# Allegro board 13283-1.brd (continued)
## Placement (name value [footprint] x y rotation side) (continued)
R2421  100KR2J-1-GP  [R402H16]  172.67 32.2 90 bottom
R2422  0R0402-PAD-2-GP  [0R0402-PAD-1]  158.07 25.06 90 top
R2423  0R0402-PAD-2-GP  [0R0402-PAD-1]  158.08 25.96 90 top
R2424  0R2J-2-GP  [R402H16]  156.92 27.26 180 top
R2425  330KR2J-L1-GP  [R402H16]  162 27.5 90 bottom
R2426  100KR2J-1-GP  [R402H16]  159.71 38.42 270 top
R2427  0R0402-PAD-2-GP  [0R0402-PAD-1]  162.89 28.39 90 bottom
R2428  0R0402-PAD-2-GP  [0R0402-PAD-1]  167.84 25.98 90 bottom
R2429  100KR2J-1-GP  [R402H16]  164.03 30.8 0 bottom
R2430  0R0402-PAD-2-GP  [0R0402-PAD-1]  158.19 33.8 0 top
R2431  330KR2J-L1-GP  [R402H16]  154.63 29.66 90 top
R2432  1KR2J-1-GP  [R402H16]  153.24 29.28 0 top
R2433  20KR2F-L-GP  [R402H16]  152.35 29.28 180 top
R2434  0R2J-2-GP  [R402H16]  167.43 27.56 180 bottom
R2435  0R0402-PAD-2-GP  [0R0402-PAD-1]  166.71 19.28 0 top
R2436  10KR2J-3-GP  [R402H16]  167.41 29.3 0 bottom
R2437  100KR2J-1-GP  [R402H16]  166.44 43.38 0 top
R2438  0R0402-PAD-2-GP  [0R0402-PAD-1]  182.44 35.32 0 top
R2439  10KR2J-3-GP  [R402H16]  154.25 24.38 90 top
R2440  0R0402-PAD-2-GP  [0R0402-PAD-1]  187.2 35.69 180 top
R2441  10KR2J-3-GP  [R402H16]  173.94 27.88 0 bottom
R2442  100KR2J-1-GP  [R402H16]  181.55 35.33 180 top
R2443  10KR2J-3-GP  [R402H16]  184.48 26.48 270 top
R2444  0R0402-PAD-2-GP  [0R0402-PAD-1]  181.69 28.2 270 top
R2445  100KR2J-1-GP  [R402H16]  181.69 27.38 90 top
R2446  64K9R2F-1-GP  [R402H16]  159.85 19.73 270 top
R2447  1KR2J-1-GP  [R402H16]  159.71 37.53 90 top
R2448  0R0402-PAD-2-GP  [0R0402-PAD-1]  32.83 83.92 0 bottom
R2449  0R0402-PAD-2-GP  [0R0402-PAD-1]  45.35 79.33 0 top
R2501  10KR2J-3-GP  [R402H16]  146.76 38.8 180 bottom
R2502  1KR2J-1-GP  [R402H16]  52.3 7.89 180 bottom
R2504  10MR2J-L-GP  [R402H16]  51.76 10.23 90 bottom
R2601  0R2J-2-GP  [R402H16]  122.25 59.5 90 top
R2602  0R2J-2-GP  [R402H16]  156.23 23.99 180 top
R2603  18K7R2F-GP  [R402H16]  127.84 61.03 270 top
R2604  2KR2F-3-GP  [R402H16]  119.07 60.39 90 top
R2605  0R2J-2-GP  [R402H16]  37.41 95.83 90 bottom
R2606  0R0402-PAD-2-GP  [0R0402-PAD-1]  41.09 93.92 180 bottom
R2607  0R3J-0-U-GP  [R603H22]  170 21.66 90 bottom
R2610  NTC-100K-8-GP  [NTC-603H38]  127.96 63.82 180 top
R2611  24K3R2F-1-GP  [R402H16]  129.11 61.54 180 top
R2612  0R0402-PAD-2-GP  [0R0402-PAD-1]  169.87 26.1 270 bottom
R2622  24K3R2F-1-GP  [R402H16]  129.99 61.54 180 top
R2624  2KR2F-3-GP  [R402H16]  171.02 22.8 90 bottom
R2701  0R0402-PAD-2-GP  [0R0402-PAD-1]  29.64 5.91 0 bottom
R2702  0R0805-PAD-2-GP-U  [0R0805-PAD-1-U]  45.09 3.55 270 top
R2703  0R0603-PAD-2-GP-U  [0R0603-PAD-1-U]  25.09 22.17 0 bottom
R2704  0R0805-PAD-2-GP-U  [0R0805-PAD-1-U]  45.09 5.45 270 top
R2705  0R0402-PAD-2-GP  [0R0402-PAD-1]  31.49 4.39 180 top
R2706  0R0805-PAD-2-GP-U  [0R0805-PAD-1-U]  37.08 20.24 90 top
R2707  20KR2F-L-GP  [R402H16]  37.03 15.94 180 top
R2708  0R0402-PAD-2-GP  [0R0402-PAD-1]  41.91 4.69 270 top
R2709  200KR2F-L-GP  [R402H16]  37.92 15.94 180 top
R2711  100KR2J-1-GP  [R402H16]  29.79 13.4 180 bottom
R2712  0R0402-PAD-2-GP  [0R0402-PAD-1]  30.67 20.92 180 top
R2714  0R0402-PAD-2-GP  [0R0402-PAD-1]  41.37 7.69 270 top
R2716  100R2J-2-GP  [R402H14]  41.37 8.53 270 top
R2717  1KR2J-1-GP  [R402H16]  39.62 17.19 270 top
R2718  0R0402-PAD-2-GP  [0R0402-PAD-1]  41.86 12.77 270 top
R2719  0R0402-PAD-2-GP  [0R0402-PAD-1]  40.08 10.61 90 bottom
R2720  0R0402-PAD-2-GP  [0R0402-PAD-1]  41.32 10.49 270 top
R2722  100KR2J-1-GP  [R402H16]  37.36 14.04 270 bottom
R2901  0R0603-PAD-2-GP-U  [0R0603-PAD-1-U]  79.45 2.68 270 top
R2902  0R0603-PAD-2-GP-U  [0R0603-PAD-1-U]  79.51 4.35 270 top
R2903  0R0603-PAD-2-GP-U  [0R0603-PAD-1-U]  79.37 7.59 270 top
R2904  0R0603-PAD-2-GP-U  [0R0603-PAD-1-U]  79.37 6.24 270 top
R2905  100KR2J-1-GP  [R402H16]  19.63 8.58 180 bottom
R2906  0R0603-PAD-2-GP-U  [0R0603-PAD-1-U]  18.11 5.15 180 top
R2907  0R0603-PAD-2-GP-U  [0R0603-PAD-1-U]  25.73 4.77 180 top
R2908  10R2F-L-GP  [R402H14]  29.3 9.73 270 top
R2909  0R0603-PAD-2-GP-U  [0R0603-PAD-1-U]  26.49 7.43 90 top
R2910  10R2F-L-GP  [R402H14]  27.63 8.58 270 top
R2911  0R0603-PAD-2-GP-U  [0R0603-PAD-1-U]  25.47 11.88 90 top
R2912  4K7R2J-2-GP  [R402H16]  29.3 10.62 270 top
R2913  4K7R2J-2-GP  [R402H16]  27.76 12.22 270 top
R2914  0R0603-PAD-2-GP-U  [0R0603-PAD-1-U]  22.17 10.86 270 bottom
R2915  470KR2J-2-GP  [R402H16]  31.06 19.5 90 bottom
R2917  0R2J-2-GP  [R402H16]  41.35 16.32 270 top
R2918  100KR2J-1-GP  [R402H16]  37.51 18 90 top
R2919  10KR2J-3-GP  [R402H16]  26.87 15.56 90 top
R2920  10KR2J-3-GP  [R402H16]  26.36 18.1 180 top
R2921  1KR2J-1-GP  [R402H16]  27.25 18.1 0 top
R2922  1KR2J-1-GP  [R402H16]  26.87 16.83 270 top
R2924  0R0402-PAD-2-GP  [0R0402-PAD-1]  18.49 8.7 0 top
R2925  10KR2J-3-GP  [R402H16]  19.38 8.7 180 top
R3001  0R3J-0-U-GP  [R603H22]  27.83 40.16 180 bottom
R3003  10KR2J-3-GP  [R402H16]  38.3 41.6 180 top
R3004  10KR2J-3-GP  [R402H16]  43.25 41.98 180 top
R3005  0R0402-PAD-2-GP  [0R0402-PAD-1]  43.25 43.76 0 top
R3006  0R0603-PAD-2-GP-U  [0R0603-PAD-1-U]  32.77 38.31 0 bottom
R3014  1KR2J-1-GP  [R402H16]  37.41 41.6 180 top
R3015  15KR2J-1-GP  [R402H16]  36.52 42.23 180 top
R3016  0R0603-PAD-2-GP-U  [0R0603-PAD-1-U]  37.16 38.42 270 top
R3021  10KR2J-3-GP  [R402H16]  44.9 47.82 0 top
R3022  20KR2J-L2-GP  [R402H16]  43.63 47.44 270 top
R3023  100KR2J-1-GP  [R402H16]  46.81 52.27 0 top
R3032  2K49R2F-GP  [R402H16]  30.39 48.31 270 bottom
R3033  10KR2J-3-GP  [R402H16]  35.94 38.27 180 bottom
R3408  0R0402-PAD-2-GP  [0R0402-PAD-1]  24.61 28.49 270 bottom
R3409  0R0402-PAD-2-GP  [0R0402-PAD-1]  24.61 27.47 270 bottom
R3410  0R0402-PAD-2-GP  [0R0402-PAD-1]  28.09 25.65 270 bottom
R3411  0R0402-PAD-2-GP  [0R0402-PAD-1]  28.09 24.79 270 bottom
R3501  100KR2J-1-GP  [R402H16]  19.84 27.12 0 top
R3502  100KR2J-1-GP  [R402H16]  160.22 5 180 bottom
R3602  200KR2J-L1-GP  [R402H16]  152.06 24.25 180 top
R3603  1KR2J-1-GP  [R402H16]  151.24 24.25 180 top
R3604  0R0402-PAD-2-GP  [0R0402-PAD-1]  137.36 65.47 180 top
R3605  0R0402-PAD-2-GP  [0R0402-PAD-1]  138.25 65.47 180 top
R3609  0R0402-PAD-2-GP  [0R0402-PAD-1]  131.82 10.64 180 top
R3624  1KR2J-1-GP  [R402H16]  137.87 63.19 270 top
R3625  100KR2J-1-GP  [R402H16]  29.08 22.57 180 top
R3626  100KR2J-1-GP  [R402H16]  29.08 24.3 180 top
R3627  0R0402-PAD-2-GP  [0R0402-PAD-1]  138.5 61.03 270 top
R5201  0R0402-PAD-2-GP  [0R0402-PAD-1]  34.36 81.22 90 top
R5202  100KR2J-1-GP  [R402H16]  52.47 75.43 90 top
R5203  0R0402-PAD-2-GP  [0R0402-PAD-1]  32.18 79.86 0 top
R5204  0R0402-PAD-2-GP  [0R0402-PAD-1]  31.34 79.86 0 top
R5205  0R0402-PAD-2-GP  [0R0402-PAD-1]  34.81 83.88 0 bottom
R5206  0R0402-PAD-2-GP  [0R0402-PAD-1]  43.38 88.71 90 bottom
R5207  0R2J-2-GP  [R402H16]  19.73 86.94 270 bottom
R5208  10KR2J-3-GP  [R402H16]  36.4 86.56 0 bottom
R5209  0R2J-2-GP  [R402H16]  37.28 86.56 180 bottom
R5210  100R2J-2-GP  [R402H14]  35.51 86.56 0 bottom
R5211  0R5J-5-GP  [R805H24]  46.99 78.07 0 top
R5219  0R2J-2-GP  [R402H16]  29.02 88.2 270 bottom
R5221  0R2J-2-GP  [R402H16]  29.02 89.21 270 bottom
R5222  0R0402-PAD-2-GP  [0R0402-PAD-1]  41.6 88.71 270 bottom
R5229  0R3J-0-U-GP  [R603H22]  33.5 68.6 270 top
R5230  0R0603-PAD-2-GP-U  [0R0603-PAD-1-U]  31.95 70.55 180 top
R5231  0R3J-0-U-GP  [R603H22]  33.25 70.56 180 top
R5232  0R3J-0-U-GP  [R603H22]  29.76 77.25 90 top
R5233  100R2J-2-GP  [R402H14]  44.47 77.72 0 top
R5401  0R0402-PAD-2-GP  [0R0402-PAD-1]  16.71 78.55 90 bottom
R5402  0R0402-PAD-2-GP  [0R0402-PAD-1]  16.71 77.67 90 bottom
R5403  0R0402-PAD-2-GP  [0R0402-PAD-1]  16.71 80.71 90 bottom
R5404  0R0402-PAD-2-GP  [0R0402-PAD-1]  16.71 79.82 90 bottom
R5405  0R0402-PAD-2-GP  [0R0402-PAD-1]  16.71 84.9 90 bottom
R5406  0R0402-PAD-2-GP  [0R0402-PAD-1]  16.71 84.02 90 bottom
R5407  0R0402-PAD-2-GP  [0R0402-PAD-1]  16.71 82.87 90 bottom
R5408  0R0402-PAD-2-GP  [0R0402-PAD-1]  16.71 81.98 90 bottom
R5409  0R3J-0-U-GP  [R603H22]  24.33 91.89 90 bottom
R5410  200KR2F-L-GP  [R402H16]  48.97 56.33 90 bottom
R5411  150KR2F-L-GP  [R402H16]  48.97 55.44 90 bottom
R5412  10KR2J-3-GP  [R402H16]  48.97 54.55 270 bottom
R5413  100KR2J-1-GP  [R402H16]  24.2 76.9 270 top
R5414  150R2J-L1-GP-U  [R402H16]  15.31 78.05 180 bottom
R5415  150R2J-L1-GP-U  [R402H16]  15.31 84.4 180 bottom
R5416  150R2J-L1-GP-U  [R402H16]  15.31 80.33 180 bottom
R5417  150R2J-L1-GP-U  [R402H16]  15.31 82.49 180 bottom
R5418  0R2J-2-GP  [R402H16]  21.92 81.48 270 top
R5419  0R0402-PAD-2-GP  [0R0402-PAD-1]  48.97 53.66 90 bottom
R5602  0R0402-PAD-2-GP  [0R0402-PAD-1]  195.53 82.11 90 bottom
R5604  10KR2J-3-GP  [R402H16]  198.19 78.05 0 top
R5610  100KR2J-1-GP  [R402H16]  197.32 78.02 0 top
R5801  0R2J-2-GP  [R402H16]  191.34 24.58 0 top
R5802  0R0402-PAD-2-GP  [0R0402-PAD-1]  172.03 16.76 90 bottom
R5803  0R0402-PAD-2-GP  [0R0402-PAD-1]  172.03 15.89 270 bottom
R5804  0R2J-2-GP  [R402H16]  168.98 20.26 270 top
R5805  0R0402-PAD-2-GP  [0R0402-PAD-1]  190.45 24.58 0 top
R5806  0R2J-2-GP  [R402H16]  189.56 26.36 0 top
R5807  0R2J-2-GP  [R402H16]  192.22 24.58 0 top
R5808  10KR2J-3-GP  [R402H16]  185.62 39.95 90 top
R6101  330R2J-3-GP  [R402H16]  180.06 17.87 270 top
R6102  100R2J-2-GP  [R402H14]  96.34 141.44 180 bottom
R6103  499R2F-2-GP  [R402H16]  180.06 17.04 270 top
R6104  0R0402-PAD-2-GP  [0R0402-PAD-1]  176.91 19.42 180 top
R6105  0R0402-PAD-2-GP  [0R0402-PAD-1]  171.14 19.83 90 top
R6201  1KR2J-1-GP  [R402H16]  193.75 87.57 180 top
R6202  0R0402-PAD-2-GP  [0R0402-PAD-1]  193.75 85.79 180 top
R6205  0R3J-0-U-GP  [R603H22]  124.41 101.41 0 top
R6206  51KR2J-1-GP  [R402H16]  140.92 78.05 180 top
R6207  100KR2J-1-GP  [R402H16]  141.81 78.05 180 top
R6208  100KR2J-1-GP  [R402H16]  133.42 64.84 90 top
R6209  0R0603-PAD-2-GP-U  [0R0603-PAD-1-U]  136.98 79.32 270 top
R6210  0R0402-PAD-2-GP  [0R0402-PAD-1]  132.88 79.08 180 top
R6211  0R0402-PAD-2-GP  [0R0402-PAD-1]  133.8 79.06 180 top
R6212  0R0402-PAD-2-GP  [0R0402-PAD-1]  129.16 96.46 270 bottom
R6213  0R0402-PAD-2-GP  [0R0402-PAD-1]  129.16 97.32 270 bottom
R6303  0R0402-PAD-2-GP  [0R0402-PAD-1]  171.65 14.04 270 top
R6304  0R0402-PAD-2-GP  [0R0402-PAD-1]  171.65 15.05 90 top
R6501  0R2J-2-GP  [R402H16]  160.23 13.55 0 top
R6502  0R2J-2-GP  [R402H16]  158.82 15.31 270 top
R7301  3KR2J-2-GP  [R402H16]  174.83 118.69 180 top
R7304  10KR2J-3-GP  [R402H16]  172.39 118.94 90 top
R7305  10KR2J-3-GP  [R402H16]  180.79 117.8 270 bottom
R7311  5K1R2F-2-GP  [R402H16]  180.79 123.13 270 bottom
R7314  100KR2J-L-GP  [R402H16]  172.39 117.97 90 top
R7315  10KR2J-3-GP  [R402H16]  180.79 116.15 0 bottom
R7317  1KR2F-3-GP  [R402H16]  171.52 121.99 0 top
R7318  1KR2F-3-GP  [R402H16]  158.06 116.15 180 top
R7320  0R0402-PAD-2-GP  [0R0402-PAD-1]  158.82 99.84 270 bottom
R7321  1K69R2F-2-GP  [R402H16]  158.9 116.15 180 top
R7322  10KR2J-3-GP  [R402H16]  182.7 118.81 180 bottom
R7323  10KR2J-3-GP  [R402H16]  182.06 121.35 270 bottom
R7324  10KR2J-3-GP  [R402H16]  180.79 122.24 270 bottom
R7325  10KR2J-3-GP  [R402H16]  183.97 120.72 270 bottom
R7326  0R0402-PAD-2-GP  [0R0402-PAD-1]  164.21 98.52 180 bottom
R7327  10KR2J-3-GP  [R402H16]  164.21 100.25 180 bottom
R7332  1KR2F-3-GP  [R402H16]  180.79 124.02 90 bottom
R7401  2K2R2J-2-GP  [R402H16]  173.05 152.72 270 top
R7402  49D9R2F-GP  [R402H16]  171.78 153.1 0 top
R7404  5K1R2F-2-GP  [R402H16]  173.05 154.5 270 top
R7408  120R2F-GP  [R402H16]  155.01 121.86 90 top
R7409  120R2F-GP  [R402H16]  159.08 122.75 270 top
R7410  40D2R2F-GP  [R402H16]  149.04 125.67 90 top
R7411  40D2R2F-GP  [R402H16]  149.04 126.69 90 top
R7414  100R2F-L1-GP-U  [R402H14]  151.2 125.29 0 top
R7415  100R2F-L1-GP-U  [R402H14]  150.31 127.07 180 top
R7418  51R2F-2-GP  [R402H16]  181.3 118.69 270 bottom
R7419  51R2F-2-GP  [R402H16]  175.87 123.26 90 top
R7420  10R2J-2-GP  [R402H14]  171.78 154.88 0 top
R7424  10KR2J-L-GP  [R402H15]  179.91 116.15 0 bottom
R7425  10KR2J-3-GP  [R402H16]  179.02 116.15 180 bottom
R7501  100KR2J-1-GP  [R402H16]  182.06 120.08 90 bottom
R7510  10KR2J-3-GP  [R402H16]  181.68 116.15 0 bottom
R7517  8K45R2F-2-GP  [R402H16]  161.36 109.29 270 top
R7518  0R0402-PAD-2-GP  [0R0402-PAD-1]  185.87 115.51 90 bottom
R7519  0R2J-2-GP  [R402H16]  180.16 113.48 270 bottom
R7520  4K75R2F-1-GP  [R402H16]  161.36 102.89 180 bottom
R7521  8K45R2F-2-GP  [R402H16]  161.36 110.18 270 top
R7522  2KR2F-3-GP  [R402H16]  161.36 111.07 270 top
R7523  8K45R2F-2-GP  [R402H16]  164.21 105.22 0 top
R7524  4K75R2F-1-GP  [R402H16]  160.47 108.02 0 top
R7526  4K75R2F-1-GP  [R402H16]  165.63 108.58 90 top
R7527  8K45R2F-2-GP  [R402H16]  163.45 103.29 270 bottom
R7533  10KR2J-3-GP  [R402H16]  184.1 115.51 270 bottom
R7710  150R2F-4-L-GP  [R402H16]  166.09 109.49 90 top
R7727  1MR2J-1-GP  [R402H16]  154.89 103.24 90 bottom
R7801  243R2F-2-GP  [R402H16]  159.33 137.23 0 bottom
R7802  243R2F-2-GP  [R402H16]  156.79 153.23 0 top
R7803  40D2R2F-GP  [R402H16]  156.79 153.23 0 bottom
R7804  40D2R2F-GP  [R402H16]  157.68 153.23 0 bottom
R7805  2K1R2F-GP  [R402H16]  153.74 152.85 270 bottom
R7806  2K1R2F-GP  [R402H16]  155.01 153.23 0 bottom
R8301  0R2J-2-GP  [R402H16]  135.89 102.05 0 bottom
R8309  15KR2J-1-GP  [R402H16]  134.62 101.59 270 bottom
R8310  15KR2J-1-GP  [R402H16]  134.62 102.48 270 bottom
R8901  2K1R2F-GP  [R402H16]  176.35 152.85 90 top
R8902  2K1R2F-GP  [R402H16]  177.62 153.23 180 top
R8903  243R2F-2-GP  [R402H16]  176.73 153.23 180 bottom
R8904  243R2F-2-GP  [R402H16]  176.98 137.23 180 top
R8907  40D2R2F-GP  [R402H16]  179.4 153.23 0 bottom
R8908  40D2R2F-GP  [R402H16]  180.29 153.23 0 bottom
RJ45  RJ45-8P-165-GP  [C100HR-10805-L]  7.88 62.7 90 bottom
RN401  SRN2K2J-1-GP  [ARES2H16]  70.94 79.82 270 bottom
RN402  SRN4K7J-8-GP  [SMD-ARES4H18]  67.13 87.57 90 top
RN404  SRN1KJ-4-GP  [ARES8-CN24H20]  65.1 77.79 90 top
RN405  SRN1KJ-4-GP  [ARES8-CN24H20]  68.53 81.73 270 top
RN407  SRN1KJ-4-GP  [ARES8-CN24H20]  65.1 80.59 270 top
RN408  SRN1KJ-11-GP-U  [SMD-ARES4-2H18-U]  77.04 83.38 270 bottom
RN601  SRN2K2J-1-GP  [ARES2H16]  120.22 78.43 270 bottom
RN602  SRN100KJ-6-GP  [SMD-ARES4]  123.77 87.7 90 bottom
RN603  SRN10KJ-5-GP  [ARES2H18]  117.29 86.56 0 bottom
RN604  SRN10KJ-6-GP  [ARES8-CN24-MUH20]  116.46 97.43 270 bottom
RN1901  0R8P4R-PAD-1-GP  [0R8P4R-PAD-1]  112.09 99.38 270 bottom
RN1902  -  [0R4P2R-PAD]  99.64 98.49 0 bottom
RN1903  -  [0R4P2R-PAD]  70.18 76.9 90 bottom
RN1904  SRN10KJ-5-GP  [ARES2H18]  119.45 90.11 180 top
RN1905  -  [0R4P2R-PAD]  96.72 98.75 0 bottom
RN2401  SRN4K7J-8-GP  [SMD-ARES4H18]  156.34 38.98 180 top
RN2501  SRN10KJ-5-GP  [ARES2H18]  152.06 36.59 0 bottom
RN2601  SRN0J-6-GP  [SMD-ARES4H20]  63.07 81.86 180 top
RN2602  SRN2K2J-1-GP  [ARES2H16]  65.86 84.78 270 top
RN2701  -  [0R4P2R-PAD]  40.59 23.18 180 top
RN2901  SRN2K2J-1-GP  [ARES2H16]  34.59 18.05 180 top
RN3001  SRN10KJ-5-GP  [ARES2H18]  37.46 35.98 270 top
RN3101  SRN75J-1-GP  [ARES8-CN24H22]  21.92 46.93 180 top
RN4301  SRN100J-4-GP  [ARES8-CN24H20]  137.61 142.94 0 top
RN5201  SRN100J-4-GP  [ARES8-CN24H20]  39.57 87.19 90 bottom
RN5202  SRN33J-5-GP-U  [SMD-ARES4H18]  28.09 85.8 90 bottom
RN5203  SRN100KJ-5-GP  [ARES8-CN24H20]  46.17 74.62 0 top
RN5204  SRN33J-5-GP-U  [SMD-ARES4H18]  32.41 85.78 270 bottom
RN5205  SRN0J-6-GP  [SMD-ARES4H20]  42.11 66.11 90 bottom
RN5206  -  [0R4P2R-PAD]  42.11 66.11 270 top
RN5401  SRN2K2J-1-GP  [ARES2H16]  21.99 90.8 0 bottom
RN5402  SRN499F-GP  [ARES8-CN24H20]  20.01 83.13 90 top
RN5403  SRN499F-GP  [ARES8-CN24H20]  20.01 79.57 90 top
RN5404  SRN2K2J-1-GP  [ARES2H16]  15.47 91.25 270 bottom
RN5601  SRN10KJ-5-GP  [ARES2H18]  194.89 79.95 180 bottom
RN6201  SRN4K7J-8-GP  [SMD-ARES4H18]  122.12 97.6 270 bottom
RN6203  SRN10KJ-5-GP  [ARES2H18]  136.6 76.93 90 top
RN6501  SRN0J-7-GP-U  [ARES8-CN24H22]  162.1 13.7 180 top
RN6502  SRN10KJ-6-GP  [ARES8-CN24-MUH20]  53.39 68.09 90 top
RN7501  SRN4K7J-8-GP  [SMD-ARES4H18]  181.18 107.76 180 bottom
RTC1  BAT-060003HA002M213ZL-GP-U1  [060003HA002M213ZL-U2]  60.75 12.32 180 top
S1  STF237R117H83-1-GP  [STF237R117H83]  200.02 96.03 180 bottom
S2  STF237R117H83-1-GP  [STF237R117H83]  141.32 131.36 180 bottom
SPI25  W25Q64FVSSIQ-GP  [SOIC8-1H86]  149.3 44.77 90 bottom
SPK1  ACES-CON4-29-GP  [50224-0040N-001]  86.55 2.4 0 top
SPR2  SPRING-102-GP  [SPR5930H154]  49.9 40.71 0 top
SPR4  SPRING-43-GP-U  [SPR4527H308]  123.2 51.9 180 bottom
SPR5  SPRING-102-GP  [SPR5930H154]  56.9 77.7 0 bottom
SPR6  SPRING-57-GP  [SPR9537H308]  72.92 13.93 0 bottom
SW1  ETY-CON4-34-GP  [6916K-Q04M-00L]  94.9 135.7 270 top
TC3501  SC100U6D3V6MX-GP  [C1206H71]  19.17 30.29 180 top
TC3502  SC100U6D3V6MX-GP  [C1206H71]  19.94 39.95 0 top
TC6301  SC100U6D3V6MX-GP  [C1206H71]  182.22 5.86 180 bottom
THM26  W83L771AWG-2-GP  [MSOP8-1H44]  123.26 62.04 270 top
TP401  TPAD14-OP-GP  [TPAD14-OP]  90.7 79.24 0 top
TP402  TPAD14-OP-GP  [TPAD14-OP]  90.45 77.92 0 top
TP403  TPAD14-OP-GP  [TPAD14-OP]  87.07 80.46 0 top
TP404  TPAD14-OP-GP  [TPAD14-OP]  78.43 77.28 180 bottom
TP409  TPAD14-OP-GP  [TPAD14-OP]  89.23 75.91 0 top
TP410  TPAD14-OP-GP  [TPAD14-OP]  107.9 75 0 top
TP411  TPAD14-OP-GP  [TPAD14-OP]  106.63 75 0 top
TP416  TPAD14-OP-GP  [TPAD14-OP]  103.2 88.97 0 top
TP417  TPAD14-OP-GP  [TPAD14-OP]  101.95 90.82 0 top
TP418  TPAD14-OP-GP  [TPAD14-OP]  94.31 77.32 0 top
TP420  TPAD14-OP-GP  [TPAD14-OP]  93.16 76.4 0 top
TP421  TPAD14-OP-GP  [TPAD14-OP]  105.23 78.17 0 top
TP433  TPAD14-OP-GP  [TPAD14-OP]  88.34 82.62 0 top
TP434  TPAD14-OP-GP  [TPAD14-OP]  87.2 81.73 0 top
TP1901  TPAD14-OP-GP  [TPAD14-OP]  110.44 97.48 180 bottom
TP1902  TPAD14-OP-GP  [TPAD14-OP]  110.44 77.79 0 top
TP1903  TPAD14-OP-GP  [TPAD14-OP]  107.36 97.48 180 bottom
TP1904  TPAD14-OP-GP  [TPAD14-OP]  105.23 91.76 0 top
TP2401  TPAD14-OP-GP  [TPAD14-OP]  166.9 30.8 180 bottom
TP2402  TPAD14-OP-GP  [TPAD14-OP]  166.04 28.19 180 bottom
TP2702  TPAD14-OP-GP  [TPAD14-OP]  39.03 6.08 270 top
TP3001  TPAD14-OP-GP  [TPAD14-OP]  27.84 42.01 270 bottom
TP3002  TPAD14-OP-GP  [TPAD14-OP]  26.69 42.58 90 bottom
TP3003  TPAD14-OP-GP  [TPAD14-OP]  32.42 43.31 90 bottom
TP5801  TPAD14-OP-GP  [TPAD14-OP]  191.45 44.29 180 bottom
TP5802  TPAD14-OP-GP  [TPAD14-OP]  191.14 32.9 180 bottom
TP5803  TPAD14-OP-GP  [TPAD14-OP]  178.43 21.81 180 bottom
TP5804  TPAD14-OP-GP  [TPAD14-OP]  178.46 20.57 180 bottom
TP7501  TPAD14-OP-GP  [TPAD14-OP]  165.86 111.65 0 top
TP7502  TPAD14-OP-GP  [TPAD14-OP]  180.54 119.83 180 bottom
TP7503  TPAD14-OP-GP  [TPAD14-OP]  179.27 119.83 180 bottom
TP7504  TPAD14-OP-GP  [TPAD14-OP]  179.27 123.64 180 bottom
TP7505  TPAD14-OP-GP  [TPAD14-OP]  180.54 121.1 180 bottom
TP7506  TPAD14-OP-GP  [TPAD14-OP]  179.27 121.1 180 bottom
TP7507  TPAD14-OP-GP  [TPAD14-OP]  172.54 120.21 0 top
TP7508  TPAD14-OP-GP  [TPAD14-OP]  179.27 122.37 180 bottom
TP7509  TPAD14-OP-GP  [TPAD14-OP]  179.27 117.67 180 bottom
TP7510  TPAD14-OP-GP  [TPAD14-OP]  165.55 112.84 0 top
TP7511  TPAD14-OP-GP  [TPAD14-OP]  171.27 116.65 0 top
TP7514  TPAD14-OP-GP  [TPAD14-OP]  171.4 106.75 0 top
TP7515  TPAD14-OP-GP  [TPAD14-OP]  171.52 105.48 0 top
TP7516  TPAD14-OP-GP  [TPAD14-OP]  159.59 111.45 0 top
TP7517  TPAD14-OP-GP  [TPAD14-OP]  180.67 114.5 180 bottom
TP7518  TPAD14-OP-GP  [TPAD14-OP]  179.4 114.5 180 bottom
TP7522  TPAD14-OP-GP  [TPAD14-OP]  163.14 110.46 0 top
TP7703  TPAD14-OP-GP  [TPAD14-OP]  150.82 127.58 180 bottom
TP7704  TPAD14-OP-GP  [TPAD14-OP]  175.46 103.07 180 bottom
TP7705  TPAD14-OP-GP  [TPAD14-OP]  150.95 106.37 180 bottom
TPAD1  ACES-CON8-40-GP  [50505-0084N-002]  132.4 91.3 0 top
TR3401  FILTER-4P-6-GP  [FILTER2013-4P-1H44]  22.93 40.88 180 bottom
TR3404  FILTER-4P-6-GP  [FILTER2013-4P-1H44]  25.4 25.89 180 top
TR5208  FILTER-4P-6-GP  [FILTER2013-4P-1H44]  29.02 88.7 180 bottom
TR5209  FILTER-4P-6-GP  [FILTER2013-4P-1H44]  36.01 76.03 90 top
TR6301  FILTER-4P-6-GP  [FILTER2013-4P-1H44]  176.22 13.15 0 top
U402  NC7WV07P6X-GP  [SC70-6H44]  73.99 83.51 90 bottom
U701  TLV70215DBVR-GP  [SOT-23-5H58]  119.45 100.65 180 top
U2901  2N7002KDW-GP  [SOT-363H44]  31.57 17.47 270 bottom
U3101  TVWDF1004AD0-1-GP  [DFN10G2510H26]  33.47 55.31 270 bottom
U3102  TVWDF1004AD0-1-GP  [DFN10G2510H26]  33.47 55.31 270 top
U3401  AZC099-04S-1-GP  [SOT-6H58]  18.67 40.87 270 bottom
U3402  TVWDF1004AD0-1-GP  [DFN10G2510H26]  19.56 25.6 270 bottom
U3403  AZC099-04S-1-GP  [SOT-6H58]  21.11 24.05 270 top
U3503  G524B2T11U-GP  [SOT-23-5H58]  32.2 32.68 270 top
U3504  G524B2T11U-GP  [SOT-23-5H58]  32.2 29.02 270 top
U3505  G524B2T11U-GP  [SOT-23-5H58]  149.42 4.36 180 bottom
U3601  TPS22966DPUR-GP  [SON14J3020-G2610H34]  131.69 6.83 0 top
U3602  TLV70215DBVR-GP  [SOT-23-5H58]  26.26 22.06 90 top
U3603  TPS22966DPUR-GP  [SON14J3020-G2610H34]  132.15 64.08 90 bottom
U5201  RT9724GB-GP  [SOT-23-5H51]  49.71 75.76 180 top
U5601  TPS2001CDGNR-GP  [MSOP8-1G189157H43]  194.51 75.63 0 top
U8201  74LVC1G08GW-1-GP  [SC70-5H44]  154.25 80.46 270 top
U8302  TPS22966DPUR-GP  [SON14J3020-G2610H34]  140.15 102.05 270 bottom
USB1  SKT-USB13-151-GP  [SKT-USB13-157164]  5.28 25.1 90 bottom
USB2  SKT-USB8-14-GP  [SKT-USB8-166140-2]  1.82 43.1 90 bottom
VRAM1  MT41K256M16HA-107G-E-GP  [BGA96D0914H48]  156.59 145.19 90 top
VRAM2  MT41K256M16HA-107G-E-GP  [BGA96D0914H48]  156.59 145.19 270 bottom
VRAM3  MT41K256M16HA-107G-E-GP  [BGA96D0914H48]  179.19 145.19 270 top
VRAM4  MT41K256M16HA-107G-E-GP  [BGA96D0914H48]  179.19 145.19 90 bottom
WLAN1  SKT-MINI52P-154-GP  [MM60-52B1-KT-R550-DT]  184.9 30.7 270 bottom
X601  XTAL-32D768KHZ-17-GP  [SMD49-6914-0403H56]  105.23 102.94 0 bottom
X1902  XTAL-48MHZ-27-GP-U  [OSC-3225-4P-4H36]  92.28 100.91 0 bottom
X3001  XTAL-25MHZ-155-GP  [OSC-3225-4P-3H36]  29.03 45.41 90 bottom
X7503  XTAL-27MHZ-46-GP  [SMD-OSC12H36]  154.76 101.03 180 bottom
XF3101  XFORM-12P-48-GP  [XFORM12A127097H91]  25.47 55.82 90 bottom
XF3102  XFORM-12P-48-GP  [XFORM12A127097H91]  25.47 55.82 270 top

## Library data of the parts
AFTP2501 AFTP2502 AFTP2801-AFTP2803 AFTP2901-AFTP2904 AFTP2906-AFTP2909 AFTP3101-AFTP3108 AFTP3801-AFTP3803 AFTP3805 AFTP3806 AFTP3901-AFTP3910 AFTP5201-AFTP5214 AFTP5222 AFTP5225-AFTP5228 AFTP6201-AFTP6242 AFTP6245-AFTP6248 AFTP6801 AFTP6802 = AFTE14P-75: tolerance: ZZ.AFT14.101
BAT1 = C144LC-109A7-L-U: tolerance: 20.81925.009
C1-C3 = HOLE197R166: tolerance: ZZ.00PAD.V71
C303-C306 C441 C445 C447 C448 C452 C457 C477 C478 = C402H22: tolerance: 78.10421.2FL; signal model: C402H22_SCD1U16V2KX-3GP
C401 C402 C601 = C402H22: tolerance: 78.15124.2FL
C443 C3405 C3406 C3504 = C402H22: tolerance: 78.10421.2FL
C501 C1201 C1204 C1214 C1217 C1222-C1225 C2402-C2404 C2406-C2410 C2412 C2414 C2417 C2502 C2602 C2605 C2608-C2610 C2615 C2707 C2709 C2710 C2717 C2719 C2720 C3002 C3009 C3013 C3507 C3517 C3625 C3626 C5201 C5401 C5606 C5802 C5804 C5807 C6202-C6204 C6402 C7406 C7407 C7515 C7631 C7681 C7686 C7689 C7779 C7781 C7788 C7791 C7803 C7808 C7810-C7814 C7816-C7819 C8308 C8309 C8313 C8314 C8901 C8908 C8910-C8915 C8920 C8922 C8923 EC2601 EC2703 EC2705 EC2708 EC2709 EC9739 EC9743 EC9744 PC4510 PC4525 PC4610 PC4612 PC4613 PC4617 PC4621 PC4906 PC8324 = C402H22: tolerance: 78.10423.2FL
C502 C1203 C1205 C1221 C3601 C3602 C3618 C3619 C5202 C8302 EC2704 EC2706 EC2707 EC9707 EC9709-EC9711 EC9714 EC9745 PC4601 PC4831 PC8213 = C402H22: tolerance: 78.10224.2FL
C603 = C402H22: tolerance: 78.8R064.1FL
C604 C5208 C5214 C7729 C7730 EC2503 EC2602 EC2701 EC3101-EC3108 EC4301 EC4302 EC4305 = C402H22: tolerance: 78.10034.1FL
C605 = C402H22: tolerance: 78.10422.L1L
C701 C702 C705 C3505 C3506 C3508 C3510 C3518 PC4901 PC4904 = C603H36: tolerance: 78.10523.5BL
C703 C762 C1208 C2501 C2601 C2712 C2713 C2902 C3603 C3605 C3620 C3621 C5609 C5610 C5803 C7582 C7602 C7610 C7613 C7623 C7634 C7640 C7652 C7679 C7682 C7684 C7687 C7792 C7793 C7801 C8303 C8304 C8905 PC4916 PC4917 PC5010-PC5012 PC5015 PC8321 PC8323 = C603H38: tolerance: 78.10610.5BL
C704 C1004-C1009 C1012-C1014 C1026-C1032 C1035-C1037 C1040-C1045 C1068-C1076 C1081-C1091 C1093-C1096 C1209-C1212 C2416 C2418 C2901 C5206 C7521 C7604 C7605 C7612 C7615-C7622 C7633 C7635-C7639 C7644-C7646 C7651 C7653 C7654 C7658-C7665 C7667-C7678 C7680 C7683 C7685 C7688 C7780 EC9718-EC9738 PC5013 = C402H22: tolerance: 78.10520.5FL
C1001 C1002 C1023 C1024 C2703 C2704 C3015 C3018 C3607 C3612 C3613 C3617 C7402 C7403 C8316 C8320 PC4528 PC4829 PC5005 = C402H22: tolerance: 78.10523.5FL
C1003 C1011 C1022 C1025 C1034 C1039 C1049-C1051 C1067 C1080 C1092 = C402H22: tolerance: 78.18134.1FL
C1010 C1015 C1016 C1033 C1038 C1046 C1053-C1055 C1215 C1216 C1218-C1220 C2604 C2611 C2701 C2702 C2706 C2708 C2711 C2715 C2716 C2718 C2907 C2908 C3004 C3005 C3010 C3012 C5204 C5207 PC4515 PC4516 PC4920 = C603H36: tolerance: 78.47520.5BL
C1047 C1064-C1066 C1077-C1079 C7647-C7650 C7666 = C603H40: tolerance: 78.22610.5BL
C1056-C1063 C3003 C3007 C3008 C3017 C3019 C3021-C3025 C3503 PC4620 PC4622 PC4701-PC4704 PC4834 PC4903 PC4915 PC4921 PC8211 PC8214 PC8217-PC8219 PC8234 PC8236 = C402H20: tolerance: 78.10423.5FL
C1202 C2705 C7607-C7609 C7624 C7625 = C402H22: tolerance: 78.22510.5FL
C1213 = C603H36: tolerance: 78.47520.L0L
C1904 C1905 EC5205 EC5206 = C402H22: tolerance: 78.6R864.1FL
C2405 C2411 C2413 PC4603 PC4604 PC8202 PC8203 = C603H36: tolerance: 78.22523.5BL
C2415 EC6103 EC6105 = C402H22: tolerance: 78.22124.2FL
C2421 C7333 PC4606 = C402H22: tolerance: 78.47034.1FL
C2503 PC4210 = C402H22: tolerance: 78.47420.5FL
C2603 C2607 EC4401 = C402H22: tolerance: 78.22224.2FL
C2606 = C603H36: tolerance: 78.47134.1BL
C2616 EC2905-EC2908 PC4605 PC4611 = C402H22: tolerance: 78.10134.1FL
C2723 PC4526 PC4527 PC5014 PC8208 = C402H22: tolerance: 78.22034.1FL
C3001 C3011 = C402H22: tolerance: 78.15034.1FL
C3014 C3016 C3403 C3404 C5203 C5209-C5213 C5402-C5409 C7301-C7308 = C402H22: tolerance: 78.10423.2FL; signal model: C402H22_SCD1U10V2KX-5GP
C3101 = C1808H56: tolerance: 78.1013N.1AL
C3106 PC4203-PC4205 PC4209 PC4412 PC4425 PC8224 PC8322 = C402H22: tolerance: 78.10324.2FL
C3401 C3402 EC2501 EC2502 = C402H22: tolerance: 78.4R774.1FL
C3509 C3512-C3516 PC4923-PC4926 = C805H58: tolerance: 78.22610.51L
C5205 EC4304 EC4601 PC4401 = C603H36: tolerance: 78.10422.2BL
C5602 C5603 C5607 C5608 C5611 C5612 C5615 C5616 = C402H22: tolerance: 78.10321.2FL; signal model: C402H22_SCD01U16V2KX-3GP
C5605 = C805H54: tolerance: 78.10623.51L
C6401 = C402H22: tolerance: 78.47321.2FL
C7401 = C402H22: tolerance: 78.12134.1FL
C7516 = C402H22: tolerance: 78.10322.L0L
C7517 = C402H22: tolerance: 78.82321.2FL
C7518 C7519 = C603H36: tolerance: 78.68421.5BL
C7611 C7802 C8903 PC4902 = C402H22: tolerance: 78.10321.2FL
C7787 C7790 = C402H22: tolerance: 78.10520.LAL
C8301 = C402H22: tolerance: 78.47124.2FL
CCD1 = 4260-F08N-00R: tolerance: 20.F1261.008
CPU1 = BGA769M24D5H78: tolerance: 071.BEEMA.000U
D401 D3602 D3603 = SOT23-2D4-312H44: tolerance: 83.00016.K11
D2401 D3606 = SOD323AKH38: tolerance: 83.R2004.G8F
D2501 = SOT23-2D4-312H48: tolerance: 75.00040.A7D
D2601 D5202 PD8201 PD8308 = SOD323AKH38: tolerance: 83.R5003.H8H
D2701 D5201 = SOT23-2D6-312H46: tolerance: 75.00054.K7D
D4301-D4303 PD4203 = SOT23-2D8-312H56: tolerance: 75.03101.07D
D5401 D7301 = SOT-23-9H44: tolerance: 83.00056.Q11
DB1 = PAD-10P-177042: tolerance: ZZ.00PAD.Y41
DCIN1 = 50299-00701-W01: tolerance: 20.F1783.007
DM1 = 1932208-1-U: tolerance: 62.10017.P41
EC2901-EC2904 = C603: tolerance: 78.22224.2BL
EC4303 EC4402 EC6104 EC9701 EC9703-EC9705 EC9708 EC9712 EC9713 EC9715-EC9717 EC9740-EC9742 EC9747-EC9749 PC4402 PC4420 PC4421 PC4423 = C402H22: tolerance: 78.10422.5FL
EC5210 EC6205-EC6208 = C402H22: tolerance: 78.33034.1FL
ED2901-ED2905 = SOD-523-4H28: tolerance: 75.02025.077
F5201 = POLYSW-4633-UH63: tolerance: 69.60040.001
F5203 = POLYSW-4633-UH43: tolerance: 69.50007.A31
F5401 = POLYSW-2114H30: tolerance: 69.48001.081
F6201 = POLYSW-2114H50: tolerance: 69.50007.921
FAN1 = 3703K-Q03N-11L: tolerance: 20.F1841.003
FAN261 = SOIC8H69: tolerance: 74.05606.A71
G701 = CON2O-U: tolerance: ZZ.CON2O.XXX
GPU1 = BGA631M23H82: tolerance: 71.SUNM2.M02
H1-H3 = HOLE335R115: tolerance: ZZ.00PAD.D01
H4 = HOLE256R115: tolerance: ZZ.00PAD.D11
H5 H6 = HT85BE85R29-U-5: tolerance: ZZ.00PAD.D41
HDA27 = QFN48J6-G465H40: tolerance: 71.03234.003
HDD1 = 127043HR022M25FZR: tolerance: 022.10019.0001
HDMI1 = SKT-HDMI23-188137: tolerance: 22.10296.A31
HDT1 = PAD-20P-127058: tolerance: ZZ.00PAD.0A1
HPMIC1 = 2SJ3080-036111F: tolerance: 022.10002.0001
IOBD1 = 196353-16021-3: tolerance: 20.K0382.016
KB1 KB2 = FL4S030HT6R300-DT: tolerance: 20.K0592.030
KBC24 = LQFP128H63: tolerance: 071.00285.000G
KBLIT1 = 51575-00441-W01: tolerance: 20.K0800.004
L3001 = L2520-D820H41: tolerance: 68.4R71E.10G
L7504 L7601 L7603 L7703 L7705 = L402H22: tolerance: 68.00084.B21
L7704 = L402H24: tolerance: 68.00094.991
L7706 L7707 PR4217 PR4911 R2402 R2703 R2901-R2904 R2906 R2907 R2909 R2911 R2914 R3006 R3016 R5230 R6209 = 0R0603-PAD-1-U: tolerance: ZZ.00PAD.M21
LCD1 = 51540-04001-W01: tolerance: 20.K0678.040
LIDSW1 = SOT23-2D8-123H52: tolerance: 74.05712.0BB
LOM30 = QFN32J4-G2D9-U1H36: tolerance: 71.08111.U03
ODD1 = C185A1-11305-L-U: tolerance: 20.81152.013
PC4010 = C603H36: tolerance: 78.47422.5BL
PC4201 = C805H58: tolerance: 78.10594.41L
PC4202 PC4409 PC4419 PC4511 PC4513 PC4518 PC4519 PC4524 PC4720 PC4722 PC4734 PC4736 PC4827 PC4833 PC4913 PC4919 PC8230 = C603H36: tolerance: 78.10424.2BL
PC4206 PC4406 PC4415-PC4418 PC4426 PC4517 PC4523 PC4713 PC4715-PC4719 PC4721 PC4830 PC4912 PC8220-PC8222 = C805H56: tolerance: 78.10622.51L
PC4208 PC4403 PC4404 PC4407 PC4434 PC4623 PC4625 PC8205 = C603H36: tolerance: 78.10522.5BL
PC4408 PC4512 PC4828 PC4909 PC4911 PC4914 = C805H54: tolerance: 78.47522.51L
PC4411 = C402H22: tolerance: 78.47322.2FL
PC4413 PC4742 PC4743 PC8232 = C603H36: tolerance: 78.33224.2BL
PC4422 = C402H22: tolerance: 78.22134.1FL
PC4501 PC4502 PC4832 = C402H22: tolerance: 78.18034.1FL
PC4514 PC4521 PC4838 = C603: tolerance: 78.56124.2BL
PC4520 = C603H32: tolerance: 78.10524.5BL
PC4609 = C402H22: tolerance: 78.68034.1FL
PC4618 PC8216 = C402H22: tolerance: 78.10590.4FL
PC4918 = C402H22: tolerance: 78.22423.5FL
PC4922 = C402H22: tolerance: 78.33124.2FL
PC8209 = C402H22: tolerance: 78.27134.1FL
PC8215 PR4634 = R402H16: tolerance: 64.14025.6DL
PD4201 = D5436AKH97: tolerance: 83.P6SBM.AAG
PD4204 = SOT-23-10H44: tolerance: 83.0024V.0A1
PD4302 = SOD123FLAKH40: tolerance: 83.SMF18.0AH
PD4401 = SOD323AKH42: tolerance: 83.1R504.A8F
PD4404 = SOD323AKH42: tolerance: 83.04148.D1H
PD4505 = SOD-323-1UH40: tolerance: 83.5R103.E3F
PD8307 = SOD323AKH44: tolerance: 083.55130.008F
PG4153 PG4402 PG4403 PG4407-PG4415 PG4502-PG4505 PG4511-PG4532 PG4535 PG4701-PG4704 PG4707-PG4712 PG4716-PG4720 PG4824-PG4828 PG4830-PG4832 PG4834 PG4837 PG4838 PG4901-PG4911 PG4913-PG4919 PG5009-PG5014 PG8203-PG8210 PG8219 PG8220 PG8316-PG8319 = GAP-CLOSE-PWR-3: tolerance: ZZ.CLOSE.001
PL4401 = L686647H119: tolerance: 68.5R610.10U
PL4501 = L736630H119: tolerance: 68.3R310.20A
PL4502 PL4802 PL5002 = L736630-MH119: tolerance: 68.2R210.20B
PL4701 PL4702 PL8201 = L7066-1830-UH158: tolerance: 68.R3610.20W
PL4902 = L736630H119: tolerance: 68.R6810.20B
PQ4201 = SOT23DGS2D4H44: tolerance: 84.00301.A31
PQ4202 Q2603 Q3002 Q3003 Q5401 = SOT23CBE2D6H46: tolerance: 84.03904.P11
PQ4203 PQ4206 PQ4402 PQ4407 PQ4408 PQ4410 PQ4501 PQ4502 PQ4601 PQ8305 PQ8314 PQ8319 Q403 Q601 Q603 Q2601 Q6202 Q7503 U2901 = SOT-363H44: tolerance: 84.2N702.A3F
PQ4204 = SOT323CBE2D2H44: tolerance: 84.00124.H1K
PQ4205 = SOT323CBE2D2H44: tolerance: 84.00124.K1K
PQ4208 PQ8201 PQ8317 Q701 Q2401 Q2403 Q2505 Q2602 Q2901 Q3001 Q5403 = SOT23DGS2D4H44: tolerance: 84.2N702.J31
PQ4409 Q2404 = SOT23CBE2D4H44: tolerance: 84.T3906.A11
PQ8318 = SOIC8H69: tolerance: 84.04468.A37
PQ8320 Q2402 Q3004 = SOT23DGS2D4H48: tolerance: 84.02130.031
PR3622 PR4203 PR4211 PR4501 PR4835 PR8349 PR8352 R601 R603 R604 R607 R608 R617 R620 R621 R627 R630 R632-R635 R638-R641 R644 R649 R701 R702 R1913 R1918 R1920 R2401 R2412 R2414 R2415 R2418 R2436 R2439 R2441 R2443 R2501 R2919 R2920 R2925 R3003 R3004 R3021 R3033 R5208 R5412 R5604 R5808 R7304 R7305 R7315 R7322-R7325 R7327 R7425 R7510 R7533 = R402H16: tolerance: 63.10334.1DL
PR4202 PR4518 PR8229 = R402H16: tolerance: 64.15025.6DL
PR4204 R7401 = R402H16: tolerance: 63.22234.1DL
PR4205 R616 R2420 = R402H16: tolerance: 63.33034.1DL
PR4207 = R603H22: tolerance: 63.24434.15L
PR4208 = R603H22: tolerance: 63.47333.15L
PR4209 PR4212 PR4213 PR4216 PR4218 PR4403 PR4417 PR4419 PR4425 PR4428 PR4430 PR4434 PR4438 PR4469 PR4509 PR8313 PR8341 R626 R629 R642 R643 R648 R705 R706 R2413 R2421 R2426 R2429 R2437 R2442 R2445 R2711 R2722 R2905 R2918 R3023 R3501 R3502 R3625 R3626 R5202 R5413 R5610 R6207 R6208 R7501 = R402H16: tolerance: 63.10434.1DL
PR4210 PR4215 R403 R410 R411 R413 R415 R416 R422-R425 R428 R434 R504 R628 R2432 R2447 R2502 R2717 R2921 R2922 R3014 R3603 R3624 R6201 = R402H16: tolerance: 63.10234.1DL
PR4214 = R1206H28: tolerance: 63.33232.11L
PR4401 PR4435 PR4439 PR4473 PR4507 PR4519 PR4608 PR4622 PR4651 PR4652 PR4706 PR4711 PR4822 PR4903 PR8201 PR8216 PR8246 PR8250-PR8253 PR8256 PR8257 = R402H16: tolerance: 64.10025.6DL
PR4402 PR4416 = R3720H40: tolerance: 64.R0105.7FL
PR4404 = R805H24: tolerance: 63.30231.16L
PR4405 R2915 = R402H16: tolerance: 63.47434.1DL
PR4406 PR4418 PR4466 PR4468 PR4475 PR4476 PR4629 PR4636 PR4680 PR4682 PR4683 PR8206 PR8227 PR8259 PR8351 R409 R414 R622 R704 R1907 R2411 R2424 R2434 R2601 R2602 R2605 R2917 R5207 R5209 R5418 R5801 R5804 R5806 R5807 R6501 R6502 R7519 R8301 = R402H16: tolerance: 63.R0034.1DL
PR4407 = R402H16: tolerance: 64.30935.6DL
PR4408 = R805H24: tolerance: 63.10031.16L
PR4409 R703 R2607 R3001 R5229 R5231 R5232 R5409 R6205 = R603H22: tolerance: 63.00000.00L
PR4411 PR5009 = R402H16: tolerance: 64.10235.6DL
PR4412 PR4415 = R402H16: tolerance: 64.33015.6DL
PR4413 = R402H16: tolerance: 64.84525.6DL
PR4414 = R402H16: tolerance: 63.33534.1DL
PR4420 = R402H16: tolerance: 64.7R505.6DL
PR4421 PR4612 PR4627 PR4633 R2908 R2910 = R402H14: tolerance: 64.10R05.6DL
PR4422 PR4426 PR4510 PR4511 PR4603 PR4607 PR4613 PR4615 PR4623-PR4626 PR4628 PR4630-PR4632 PR4637-PR4639 PR4649 PR4661 PR4662 PR4679 PR4819 PR4821 PR4906 PR4907 PR4910 PR5010 PR8202 PR8217 PR8220 PR8222 PR8228 PR8230 PR8255 PR8269-PR8271 PR8273-PR8275 PR8328 PR8345 R404 R412 R417 R418 R602 R609-R614 R618 R625 R631 R1901 R1906 R2408-R2410 R2416 R2417 R2419 R2422 R2423 R2427 R2428 R2430 R2435 R2438 R2440 R2444 R2448 R2449 R2606 R2612 R2701 R2705 R2708 R2712 R2714 R2718-R2720 R2924 R3005 R3408-R3411 R3604 R3605 R3609 R3627 R5201 R5203-R5206 R5222 R5419 R5602 R5802 R5803 R5805 R6104 R6105 R6202 R6210-R6213 R6303 R6304 R7320 R7326 R7518 = 0R0402-PAD-1: tolerance: ZZ.00PAD.M11
PR4423 = R402H16: tolerance: 64.59025.6DL
PR4424 R7517 R7521 R7523 R7527 = R402H16: tolerance: 64.84515.6DL
PR4427 = R402H16: tolerance: 64.66525.6DL
PR4429 R5411 = R402H16: tolerance: 64.15035.6DL
PR4431 = R402H16: tolerance: 64.47025.6DL
PR4432 PR4433 PR4436 = R402H16: tolerance: 64.12035.6DL
PR4437 = R402H16: tolerance: 64.16035.6DL
PR4464 = R402H16: tolerance: 63.68434.1DL
PR4467 R1905 R7727 = R402H16: tolerance: 63.10534.1DL
PR4470 PR4515 PR4522 PR4610 PR4620 PR4674 PR5011 PR8231 R2406 R2407 = R402H16: tolerance: 64.10035.6DL
PR4502 R3602 = R402H16: tolerance: 63.20434.1DL
PR4503 = R402H16: tolerance: 64.16935.6DL
PR4504 = R402H16: tolerance: 64.36535.6DL
PR4505 PR4517 PR4837 PR4912 = R805H24: tolerance: 64.2R205.16L
PR4506 = R402H16: tolerance: 64.66515.6DL
PR4508 PR4513 = R402H16: tolerance: 63.2R234.1DL
PR4514 R2709 R5410 = R402H16: tolerance: 64.20035.6DL
PR4516 PR4659 = R402H16: tolerance: 64.39025.6DL
PR4520 = R402H16: tolerance: 64.40225.6DL
PR4521 = R402H16: tolerance: 64.75035.6DL
PR4604 PR8203 = R603H22: tolerance: 63.10033.15L
PR4609 = R402H16: tolerance: 64.49925.6DL
PR4621 = R402H16: tolerance: 64.11025.6DL
PR4645 = R402H16: tolerance: 64.37425.6DL
PR4646 = R402H16: tolerance: 64.15425.6DL
PR4648 PR5012 PR8237 = R402H16: tolerance: 64.2R205.6DL
PR4653-PR4655 PR4663 PR4681 = R402H16: tolerance: 64.13035.6DL
PR4656 = R402H16: tolerance: 64.30005.6DL
PR4657 = R402H16: tolerance: 64.12725.6DL
PR4658 PR8242 = R402H16: tolerance: 64.22025.6DL
PR4660 = R402H16: tolerance: 64.28725.6DL
PR4664 PR4671 PR4908 R301 R1903 R1904 R1909 R1910 R7317 R7318 R7332 = R402H16: tolerance: 64.10015.6DL
PR4665 PR8204 = R402H16: tolerance: 64.11535.6DL
PR4666 PR4667 PR8205 = R402H16: tolerance: 64.4R705.6DL
PR4668 = R402H16: tolerance: 64.11335.6DL
PR4669 PR8234 = R402H16: tolerance: 64.21005.6DL
PR4670 PR8232 = R402H16: tolerance: 64.12435.6DL
PR4672 PR8238 = R402H16: tolerance: 64.33025.6DL
PR4673 PR4708 PR8239 PR8265 = R402H16: tolerance: 64.75005.6DL
PR4675 PR8241 = R402H16: tolerance: 64.45305.6DL
PR4676 PR8240 = R402H16: tolerance: 64.62015.6DL
PR4677 PR4678 PR8244 = NTC-402H22-U: tolerance: 69.60037.031
PR4701 PR4702 = R603H22: tolerance: 63.R0033.15L
PR4705 PR4712 PR8263 = R402H16: tolerance: 64.30015.6DL
PR4707 = R402H16: tolerance: 64.91005.6DL
PR4709 PR4710 PR8260 = R805H24: tolerance: 64.1R005.16L
PR4817 = R402H16: tolerance: 64.10535.60L
PR4820 PR4905 R2403 = R603H22: tolerance: 64.2R205.55L
PR4823 = R402H16: tolerance: 64.26125.6DL
PR4824 = R402H16: tolerance: 64.47035.6DL
PR4901 = R402H16: tolerance: 64.30125.6DL
PR4902 = R402H16: tolerance: 64.13335.6DL
PR4904 R2433 R2707 = R402H16: tolerance: 64.20025.6DL
PR5013 = R402H16: tolerance: 64.51025.6DL
PR8214 = R402H16: tolerance: 64.49935.6DL
PR8215 = R402H16: tolerance: 64.97615.6DL
PR8233 = R402H16: tolerance: 64.10016.6DL
PR8235 = R402H16: tolerance: 64.18015.6DL
PR8245 = R402H16: tolerance: 64.30025.6DL
PR8248 PR8254 = R402H16: tolerance: 64.47015.6DL
PR8316 PR8344 R7420 = R402H14: tolerance: 63.10034.1DL
PR8347 R2504 = R402H16: tolerance: 63.10634.1DL
PR8348 R2425 R2431 = R402H16: tolerance: 63.33434.1DL
PR8350 = R402H16: tolerance: 63.47134.1DL
PT4501 PT4502 = SE361414H178: tolerance: 79.22710.3KL
PT4701 PT4704 PT4803 PT8204 PT8205 = SE361414H178: tolerance: 79.3371V.6CL
PT4702 PT4703 = CT7343H83: tolerance: 79.33719.L01
PT4705 = SE341413H241: tolerance: 79.68612.30L
PU4201 PU4402 PU4403 = PPAK-8P-3232H36: tolerance: 84.07401.037
PU4404 = QFN20G3D5-G2D15H40: tolerance: 74.24727.A73
PU4405 PU4406 PU4502-PU4504 PU4805 PU4808 PU4902 = PPAK-8P-2H45: tolerance: 84.00412.037
PU4501 = QFN20-G1D75H32: tolerance: 74.08230.043
PU4505 PU4903 = PPAK-8P-2H45: tolerance: 84.00780.037
PU4601 PU8202 = QFN40-G3D5H32: tolerance: 074.08179.0073
PU4701-PU4704 = PPAK-8P-G5324H44-COLAY: tolerance: ZZ.00215.037
PU4806 = DFN10G3-G265175H32: tolerance: 74.08237.B73
PU4901 = QFN20-G1D75H32: tolerance: 74.51716.073
PU5002 = DFN10G3-G265175H32: tolerance: 74.08068.A43
PU8203 = PPAK-5PH45: tolerance: 84.A14DP.037
PU8205 = PPAK-5PH45: tolerance: 84.SRA06.037
Q5402 = SOT-363H44: tolerance: 84.2N702.A3F; signal model: SOT-363H44_2N7002KDW-GP
Q6103 Q6104 Q6201 = SOT23-2D8-321H56: tolerance: 84.DT144.A11
Q6203 = SOT23DGS2D8H56: tolerance: 84.P8503.031
Q7504 = SOT23DGS2D4H44: tolerance: 84.07002.I31
R302 R7321 = R402H16: tolerance: 64.16915.6DL
R401 = R402H16: tolerance: 64.15005.6DL
R402 R2604 R2624 R7522 = R402H16: tolerance: 64.20015.6DL
R405 R406 R408 = R402H16: tolerance: 64.75R05.6DL
R407 R6103 = R402H16: tolerance: 64.49905.6DL
R419 R420 = R402H16: tolerance: 64.51105.6DL
R421 = R402H16: tolerance: 63.30134.1DL
R503 = R402H16: tolerance: 64.39R25.6DL
R623 = R603H22: tolerance: 63.20634.15L
R636 R637 R1911 R1915 R1927 R1929 R7424 = R402H15: tolerance: 63.10334.L0L
R645-R647 R3015 R8309 R8310 = R402H16: tolerance: 63.15334.1DL
R1902 = R402H16: tolerance: 64.11825.6DL
R1908 R1921-R1924 R5401-R5408 = 0R0402-PAD-1: tolerance: ZZ.00PAD.M11; signal model: R402H16_0R2J-2-GP
R1912 R1914 R1916 R1917 R1919 R1926 R1928 = R402H16: tolerance: 63.20234.1DL
R1925 = R402H16: tolerance: 63.33034.1DL; signal model: R402H16_33R2J-2-GP
R2404 R2446 = R402H16: tolerance: 64.64925.6DL
R2405 = R402H16: tolerance: 64.27025.6DL
R2603 = R402H16: tolerance: 64.18725.6DL
R2610 = NTC-603H38: tolerance: 69.60035.041
R2611 R2622 = R402H16: tolerance: 64.24325.6DL
R2702 R2704 R2706 = 0R0805-PAD-1-U: tolerance: ZZ.00PAD.M31
R2716 R5210 R5233 R6102 = R402H14: tolerance: 63.10134.1DL
R2912 R2913 = R402H16: tolerance: 63.47234.1DL
R3022 = R402H16: tolerance: 63.20334.1DL
R3032 = R402H16: tolerance: 64.24915.6DL
R5211 = R805H24: tolerance: 63.R0031.16L
R5219 R5221 = R402H16: tolerance: 63.R0034.1DL; signal model: R402H16_0R2J-2-GP
R5414-R5417 = R402H16: tolerance: 63.15134.1DL
R6101 = R402H16: tolerance: 63.33134.1DL
R6206 = R402H16: tolerance: 63.51334.1DL
R7301 = R402H16: tolerance: 63.30234.1DL
R7311 R7404 = R402H16: tolerance: 64.51015.6DL
R7314 = R402H16: tolerance: 63.10434.L0L
R7402 = R402H16: tolerance: 64.49R95.6DL
R7408 R7409 = R402H16: tolerance: 64.12005.6DL
R7410 R7411 R7803 R7804 R8907 R8908 = R402H16: tolerance: 64.40R25.6DL
R7414 R7415 = R402H14: tolerance: 64.10005.6DL
R7418 R7419 = R402H16: tolerance: 64.51R05.6DL
R7520 R7524 R7526 = R402H16: tolerance: 64.47515.6DL
R7710 = R402H16: tolerance: 64.15005.L0L
R7801 R7802 R8903 R8904 = R402H16: tolerance: 64.24305.6DL
R7805 R7806 R8901 R8902 = R402H16: tolerance: 64.21015.6DL
RJ45 = C100HR-10805-L: tolerance: 022.10001.0551
RN401 RN601 RN2602 RN2901 RN5401 RN5404 = ARES2H16: tolerance: 66.22236.04L
RN402 RN2401 RN6201 RN7501 = SMD-ARES4H18: tolerance: 66.47236.04L
RN404 RN405 RN407 = ARES8-CN24H20: tolerance: 66.10236.08L
RN408 = SMD-ARES4-2H18-U: tolerance: 66.1023A.04L
RN602 = SMD-ARES4: tolerance: 66.10436.04L
RN603 RN1904 RN2501 RN3001 RN5601 RN6203 = ARES2H18: tolerance: 66.10336.04L
RN604 RN6502 = ARES8-CN24-MUH20: tolerance: 66.10336.08L
RN1901 = 0R8P4R-PAD-1: tolerance: ZZ.0R08P.ZHH
RN1902 RN1903 RN1905 = 0R4P2R-PAD: tolerance: ZZ.0R04P.ZZZ; signal model: SMD-ARES4H20_SRN0J-6-GP
RN2601 = SMD-ARES4H20: tolerance: 66.R0036.04L
RN2701 RN5206 = 0R4P2R-PAD: tolerance: ZZ.0R04P.ZZZ
RN3101 = ARES8-CN24H22: tolerance: 66.75036.08L
RN4301 RN5201 = ARES8-CN24H20: tolerance: 66.10136.A8L
RN5202 RN5204 = SMD-ARES4H18: tolerance: 66.33036.04L
RN5203 = ARES8-CN24H20: tolerance: 66.10436.A8L
RN5205 = SMD-ARES4H20: tolerance: 66.R0036.04L; signal model: SMD-ARES4H20_SRN0J-6-GP
RN5402 RN5403 = ARES8-CN24H20: tolerance: 66.49156.08L
RN6501 = ARES8-CN24H22: tolerance: 66.R0036.A8L
RTC1 = 060003HA002M213ZL-U2: tolerance: 62.70014.001
S1 S2 = STF237R117H83: tolerance: 34.4CK01.001
SPI25 = SOIC8-1H86: tolerance: 72.25Q64.K01
SPK1 = 50224-0040N-001: tolerance: 20.F1639.004
SPR2 SPR5 = SPR5930H154: tolerance: 34.41V01.001
SPR4 = SPR4527H308: tolerance: 34.15J03.001
SPR6 = SPR9537H308: tolerance: 34.42T14.002
SW1 = 6916K-Q04M-00L: tolerance: 20.K0465.004
TC3501 TC3502 TC6301 = C1206H71: tolerance: 78.10710.52L
THM26 = MSOP8-1H44: tolerance: 74.83771.ABG
TP401-TP404 TP409-TP411 TP416-TP418 TP420 TP421 TP433 TP434 TP1901-TP1904 TP2401 TP2402 TP2702 TP3001-TP3003 TP5801-TP5804 TP7501-TP7511 TP7514-TP7518 TP7522 TP7703-TP7705 = TPAD14-OP: tolerance: ZZ.PAD14.001
TPAD1 = 50505-0084N-002: tolerance: 20.K0667.008
TR3401 TR3404 TR5208 TR6301 = FILTER2013-4P-1H44: tolerance: 69.10103.041; signal model: FILTER2013-4P-1H44_FILTER-4P-6-GP
TR5209 = FILTER2013-4P-1H44: tolerance: 69.10103.041
U402 = SC70-6H44: tolerance: 73.7WV07.00J
U701 U3602 = SOT-23-5H58: tolerance: 74.70215.03F
U3101 U3102 U3402 = DFN10G2510H26: tolerance: 75.01004.073
U3401 U3403 = SOT-6H58: tolerance: 75.09904.07C
U3503-U3505 = SOT-23-5H58: tolerance: 074.00524.0C9F
U3601 U3603 U8302 = SON14J3020-G2610H34: tolerance: 74.22966.093
U5201 = SOT-23-5H51: tolerance: 74.09724.09F
U5601 = MSOP8-1G189157H43: tolerance: 74.02001.079
U8201 = SC70-5H44: tolerance: 73.01G08.L04
USB1 = SKT-USB13-157164: tolerance: 22.10341.Q21
USB2 = SKT-USB8-166140-2: tolerance: 22.10321.E91
VRAM1-VRAM4 = BGA96D0914H48: tolerance: 72.41K26.00U
WLAN1 = MM60-52B1-KT-R550-DT: tolerance: 62.10043.I81
X601 = SMD49-6914-0403H56: tolerance: 82.30001.C41
X1902 = OSC-3225-4P-4H36: tolerance: 82.30026.281
X3001 = OSC-3225-4P-3H36: tolerance: 82.30020.D41
X7503 = SMD-OSC12H36: tolerance: 82.30034.351
XF3101 XF3102 = XFORM12A127097H91: tolerance: 68.68167.30D; signal model: XFORM12A127096H97_XFORM-12P-36-GP

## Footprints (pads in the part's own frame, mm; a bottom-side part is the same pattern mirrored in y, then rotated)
0R4P2R-PAD
  custom 0.089x0.089 smd: 1(-0.325,-0.599) 2(0.325,-0.599) 3(0.325,0.599) 4(-0.325,0.599)
0R8P4R-PAD-1
  rect 0.61x0.838 smd: 1(-0.9,-0.486) 4(0.9,-0.486) 5(0.9,0.486) 8(-0.9,0.486)
  rect 0.305x0.838 smd: 2(-0.25,-0.486) 3(0.25,-0.486) 6(0.25,0.486) 7(-0.25,0.486)
0R0402-PAD-1
  custom 0.14x0.14 smd: 1(0,0.445) 2(0,-0.445)
0R0603-PAD-1-U
  custom 0.254x0.254 smd: 1(0,0.66) 2(0,-0.66)
0R0805-PAD-1-U
  rect 1.549x1.333 smd: 1(0,0.838) 2(0,-0.838)
2SJ3080-036111F
  oval 1.321x2.235 hole 0.61x1.524: 1(-4.8,8.4) 2(4.7,2.9) 3(-4.8,0.6) 4(4.7,0) 5(4.7,8.4) 6(4.7,5.65) MS(-4.8,4.3)
3703K-Q03N-11L
  rect 0.61x1.549 smd: 1(-1,3.775) 2(0,3.775) 3(1,3.775)
  rect 1.194x2.007 smd: 4(-2.3,0) 5(2.3,0)
4260-F08N-00R
  rect 0.508x0.991 smd: 1(2.8,1.945) 2(2,1.945) 3(1.2,1.945) 4(0.4,1.945) 5(-0.4,1.945) 6(-1.2,1.945) 7(-2,1.945) 8(-2.8,1.945)
  rect 1.194x1.702 smd: 9(4.097,0) 10(-4.097,0)
6916K-Q04M-00L
  rect 0.305x1.295 smd: 1(-1.5,2.65) 2(-0.5,2.65) 3(0.5,2.65) 4(1.5,2.65)
  rect 1.803x1.397 smd: 5(-3.65,0) 6(3.65,0)
50224-0040N-001
  rect 0.61x1.549 smd: 1(-1.5,3.875) 2(-0.5,3.875) 3(0.5,3.875) 4(1.5,3.875)
  rect 1.194x1.803 smd: 5(-2.797,0) 6(2.797,0)
50299-00701-W01
  round 0.254 hole 1.753 unplated: (-6.2,0) (6.2,0)
  rect 0.889x2.311 smd: 1(6,5.15) 2(4,5.15) 3(2,5.15) 4(0,5.15) 5(-2,5.15) 6(-4,5.15) 7(-6,5.15)
50505-0084N-002
  rect 0.406x1.295 smd: 1(3.5,3.25) 2(2.5,3.25) 3(1.5,3.25) 4(0.5,3.25) 5(-0.5,3.25) 6(-1.5,3.25) 7(-2.5,3.25) 8(-3.5,3.25)
  rect 0.991x2.007 smd: 9(6.1,0) 10(-6.1,0)
51540-04001-W01
  rect 0.305x0.838 smd: 1(-9.75,3.175) 2(-9.25,3.175) 3(-8.75,3.175) 4(-8.25,3.175) 5(-7.75,3.175) 6(-7.25,3.175) 7(-6.75,3.175) 8(-6.25,3.175) 9(-5.75,3.175) 10(-5.25,3.175) 11(-4.75,3.175) 12(-4.25,3.175) 13(-3.75,3.175) 14(-3.25,3.175) 15(-2.75,3.175) 16(-2.25,3.175) 17(-1.75,3.175) 18(-1.25,3.175) 19(-0.75,3.175) 20(-0.25,3.175) 21(0.25,3.175) 22(0.75,3.175) 23(1.25,3.175) 24(1.75,3.175) 25(2.25,3.175) 26(2.75,3.175) 27(3.25,3.175) 28(3.75,3.175) 29(4.25,3.175) 30(4.75,3.175) 31(5.25,3.175) 32(5.75,3.175) 33(6.25,3.175) 34(6.75,3.175) 35(7.25,3.175) 36(7.75,3.175) 37(8.25,3.175) 38(8.75,3.175) 39(9.25,3.175) 40(9.75,3.175)
  rect 0.813x2.007 smd: 41(-11.45,0) 42(11.45,0)
51575-00441-W01
  rect 0.406x0.838 smd: 1(-1.5,3.175) 2(-0.5,3.175) 3(0.5,3.175) 4(1.5,3.175)
  rect 0.813x2.007 smd: 5(-3.7,0) 6(3.7,0)
060003HA002M213ZL-U2
  round 0.254 hole 1.321 unplated: (0,8)
  round 0.254 hole 1.219 unplated: (0,-8)
  custom 1.454x1.454 smd: 1(14.5,0)
  custom 1.899x1.899 smd: 2(-15.8,0)
127043HR022M25FZR
  round 0.254 hole 1.27 unplated: (-15.595,0) (15.595,0)
  oval 1.803x3.2 hole 1.016x2.413: 23(18.075,1.11) 24(-18.075,1.11)
  oval 1.041x1.168 hole 0.762: P1(1.905,1.84) P2(0.635,1.84) P3(-0.635,1.84) P4(-1.905,1.84) P5(-3.175,1.84) P6(-4.445,1.84) P7(-5.715,1.84) P8(-6.985,1.84) P9(-8.255,1.84) P10(-9.525,1.84) P11(-10.795,1.84) P12(-12.065,1.84) P13(-13.335,1.84) P14(-14.605,1.84) P15(-15.875,1.84) S1(15.875,1.84) S2(14.605,1.84) S3(13.335,1.84) S4(12.065,1.84) S5(10.795,1.84) S6(9.525,1.84) S7(8.255,1.84)
196353-16021-3
  rect 0.61x1.295 smd: 1(-7.5,2.8) 2(-6.5,2.8) 3(-5.5,2.8) 4(-4.5,2.8) 5(-3.5,2.8) 6(-2.5,2.8) 7(-1.5,2.8) 8(-0.5,2.8) 9(0.5,2.8) 10(1.5,2.8) 11(2.5,2.8) 12(3.5,2.8) 13(4.5,2.8) 14(5.5,2.8) 15(6.5,2.8) 16(7.5,2.8)
  rect 1.803x1.397 smd: 17(-9.65,0) 18(9.65,0)
1932208-1-U
  round 0.254 hole 1.118 unplated: (-33.4,0)
  round 0.254 hole 1.6 unplated: (33.4,0)
  custom 0.114x0.114 smd: 1(31.65,4.1) 2(31.35,-4.1) 3(31.05,4.1) 4(30.751,-4.1) 5(30.45,4.1) 6(30.15,-4.1) 7(29.85,4.1) 8(29.55,-4.1) 9(29.251,4.1) 10(28.95,-4.1) 11(28.65,4.1) 12(28.35,-4.1) 13(28.051,4.1) 14(27.751,-4.1) 15(27.45,4.1) 16(27.15,-4.1) 17(26.851,4.1) 18(26.551,-4.1) 19(26.25,4.1) 20(25.95,-4.1) 21(25.65,4.1) 22(25.35,-4.1) 23(25.051,4.1) 24(24.75,-4.1) 25(24.45,4.1) 26(24.15,-4.1) 27(23.851,4.1) 28(23.55,-4.1) 29(23.25,4.1) 30(22.95,-4.1) 31(22.651,4.1) 32(22.351,-4.1) 33(22.05,4.1) 34(21.75,-4.1) 35(21.451,4.1) 36(21.151,-4.1) 37(20.85,4.1) 38(20.55,-4.1) 39(20.25,4.1) 40(19.95,-4.1) 41(19.65,4.1) 42(19.35,-4.1) 43(19.049,4.1) 44(18.749,-4.1) 45(18.45,4.1) 46(18.15,-4.1) 47(17.85,4.1) 48(17.549,-4.1) 49(17.25,4.1) 50(16.95,-4.1) 51(16.65,4.1) 52(16.349,-4.1) 53(16.049,4.1) 54(15.75,-4.1) 55(15.45,4.1) 56(15.15,-4.1) 57(14.849,4.1) 58(14.549,-4.1) 59(14.25,4.1) 60(13.95,-4.1) 61(13.649,4.1) 62(13.349,-4.1) 63(13.05,4.1) 64(12.75,-4.1) 65(12.45,4.1) 66(12.149,-4.1) 67(11.85,4.1) 68(11.55,-4.1) 69(11.25,4.1) 70(10.95,-4.1) 71(10.649,4.1) 72(10.349,-4.1) 73(7.65,4.1) 74(7.35,-4.1) 75(7.049,4.1) 76(6.749,-4.1) 77(6.45,4.1) 78(6.15,-4.1) 79(5.85,4.1) 80(5.549,-4.1) 81(5.25,4.1) 82(4.95,-4.1) 83(4.65,4.1) 84(4.349,-4.1) 85(4.05,4.1) 86(3.75,-4.1) 87(3.45,4.1) 88(3.15,-4.1) 89(2.849,4.1) 90(2.549,-4.1) 91(2.25,4.1) 92(1.95,-4.1) 93(1.649,4.1) 94(1.349,-4.1) 95(1.05,4.1) 96(0.75,-4.1) 97(0.45,4.1) 98(0.149,-4.1) 99(-0.15,4.1) 100(-0.45,-4.1) 101(-0.75,4.1) 102(-1.051,-4.1) 103(-1.351,4.1) 104(-1.65,-4.1) 105(-1.95,4.1) 106(-2.25,-4.1) 107(-2.551,4.1) 108(-2.851,-4.1) 109(-3.15,4.1) 110(-3.45,-4.1) 111(-3.751,4.1) 112(-4.051,-4.1) 113(-4.35,4.1) 114(-4.65,-4.1) 115(-4.95,4.1) 116(-5.251,-4.1) 117(-5.55,4.1) 118(-5.85,-4.1) 119(-6.15,4.1) 120(-6.451,-4.1) 121(-6.751,4.1) 122(-7.051,-4.1) 123(-7.35,4.1) 124(-7.65,-4.1) 125(-7.951,4.1) 126(-8.251,-4.1) 127(-8.55,4.1) 128(-8.85,-4.1) 129(-9.15,4.1) 130(-9.451,-4.1) 131(-9.75,4.1) 132(-10.05,-4.1) 133(-10.35,4.1) 134(-10.651,-4.1) 135(-10.95,4.1) 136(-11.25,-4.1) 137(-11.55,4.1) 138(-11.85,-4.1) 139(-12.151,4.1) 140(-12.451,-4.1) 141(-12.75,4.1) 142(-13.05,-4.1) 143(-13.351,4.1) 144(-13.651,-4.1) 145(-13.95,4.1) 146(-14.25,-4.1) 147(-14.55,4.1) 148(-14.851,-4.1) 149(-15.15,4.1) 150(-15.45,-4.1) 151(-15.75,4.1) 152(-16.051,-4.1) 153(-16.35,4.1) 154(-16.65,-4.1) 155(-16.95,4.1) 156(-17.25,-4.1) 157(-17.551,4.1) 158(-17.851,-4.1) 159(-18.15,4.1) 160(-18.45,-4.1) 161(-18.751,4.1) 162(-19.051,-4.1) 163(-19.35,4.1) 164(-19.65,-4.1) 165(-19.95,4.1) 166(-20.251,-4.1) 167(-20.55,4.1) 168(-20.85,-4.1) 169(-21.15,4.1) 170(-21.451,-4.1) 171(-21.751,4.1) 172(-22.051,-4.1) 173(-22.35,4.1) 174(-22.65,-4.1) 175(-22.951,4.1) 176(-23.251,-4.1) 177(-23.55,4.1) 178(-23.85,-4.1) 179(-24.151,4.1) 180(-24.451,-4.1) 181(-24.75,4.1) 182(-25.05,-4.1) 183(-25.35,4.1) 184(-25.651,-4.1) 185(-25.95,4.1) 186(-26.25,-4.1) 187(-26.55,4.1) 188(-26.851,-4.1) 189(-27.151,4.1) 190(-27.451,-4.1) 191(-27.75,4.1) 192(-28.05,-4.1) 193(-28.351,4.1) 194(-28.651,-4.1) 195(-28.95,4.1) 196(-29.25,-4.1) 197(-29.55,4.1) 198(-29.851,-4.1) 199(-30.15,4.1) 200(-30.45,-4.1) 201(-30.75,4.1) 202(-31.05,-4.1) 203(-31.349,4.1) 204(-31.649,-4.1)
  rect 3.505x4.597 smd: 205(32.8,12) 206(-32.8,12)
